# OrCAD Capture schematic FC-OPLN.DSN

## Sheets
1 Index: title: Index
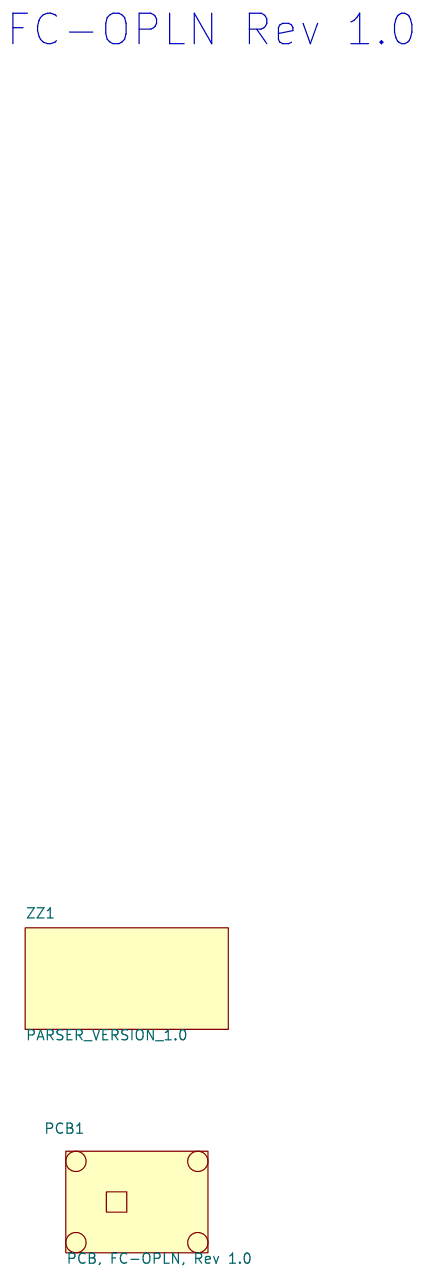
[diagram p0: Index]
2 Block Diagram: title: Block Diagram
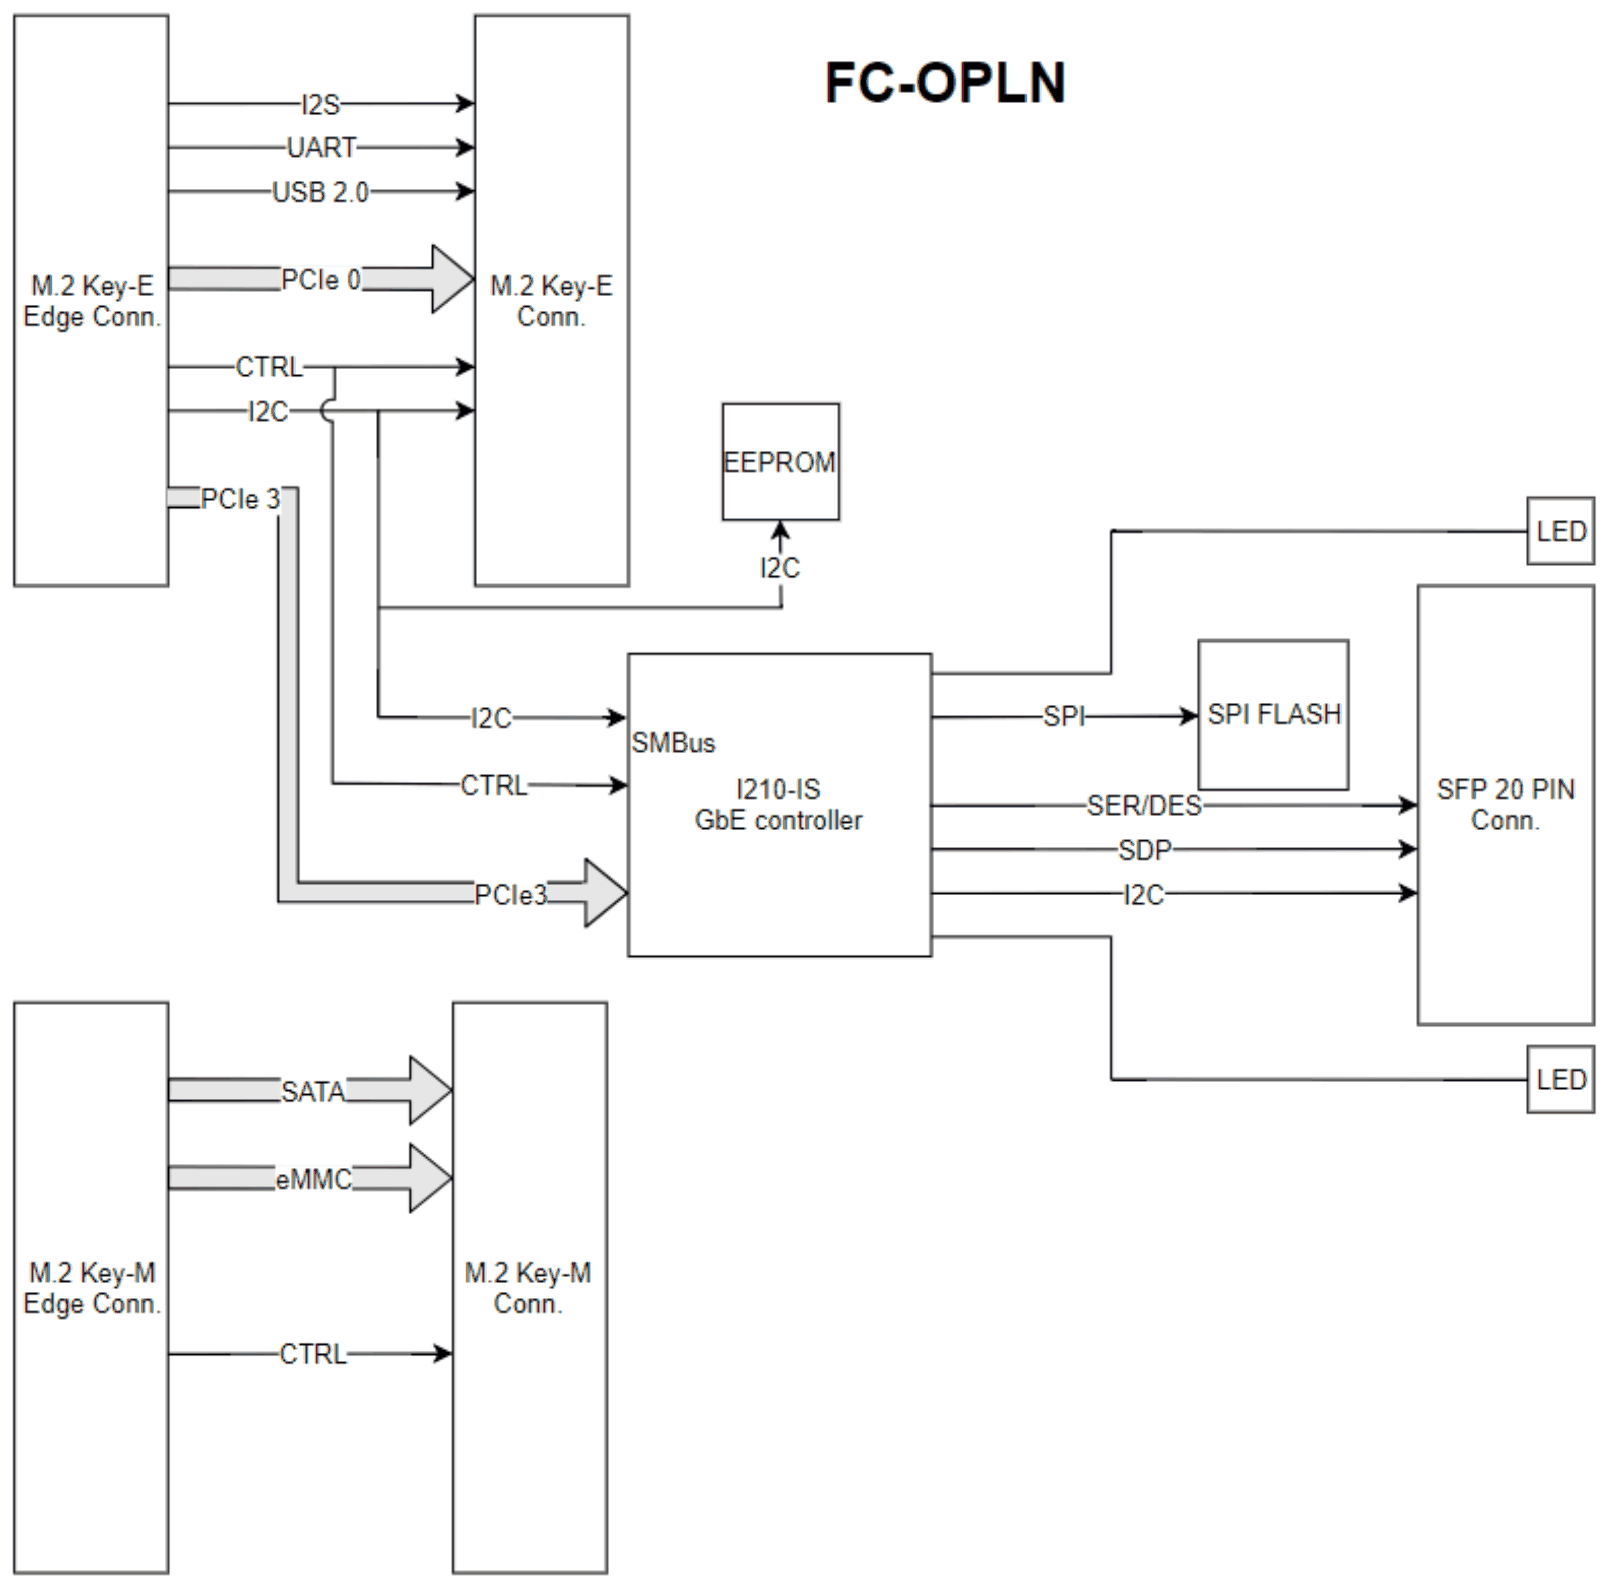
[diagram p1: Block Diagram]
3 Power Diagram
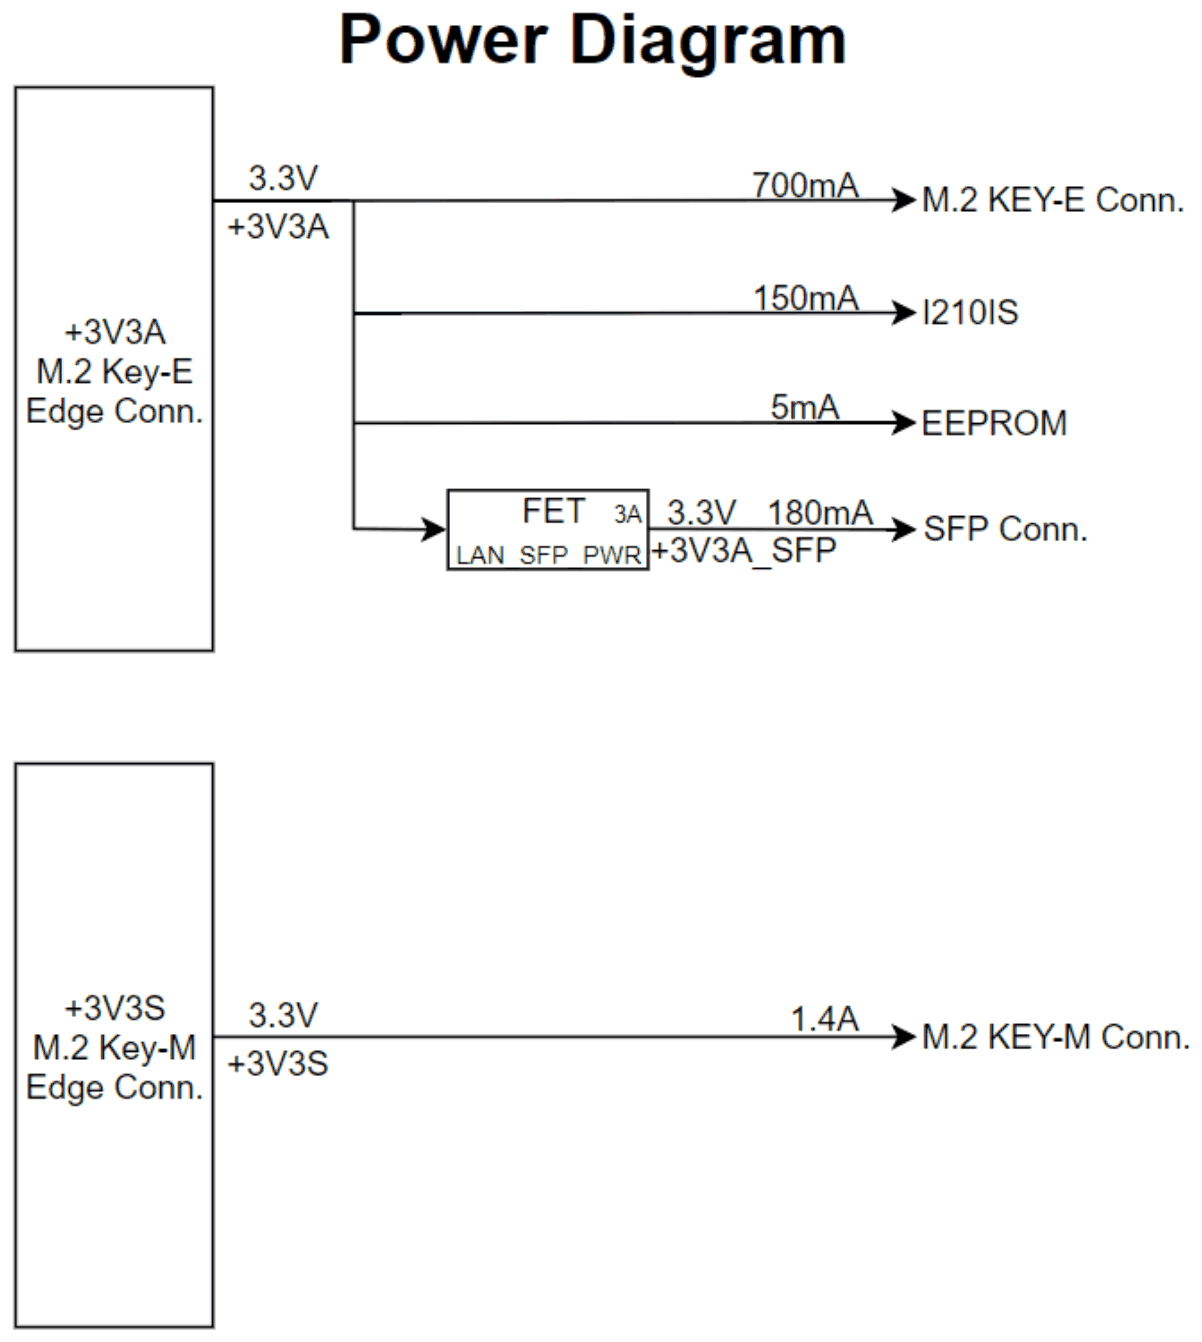
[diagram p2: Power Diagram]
4 M.2 KEY M: size A4; title: M.2 KEY M
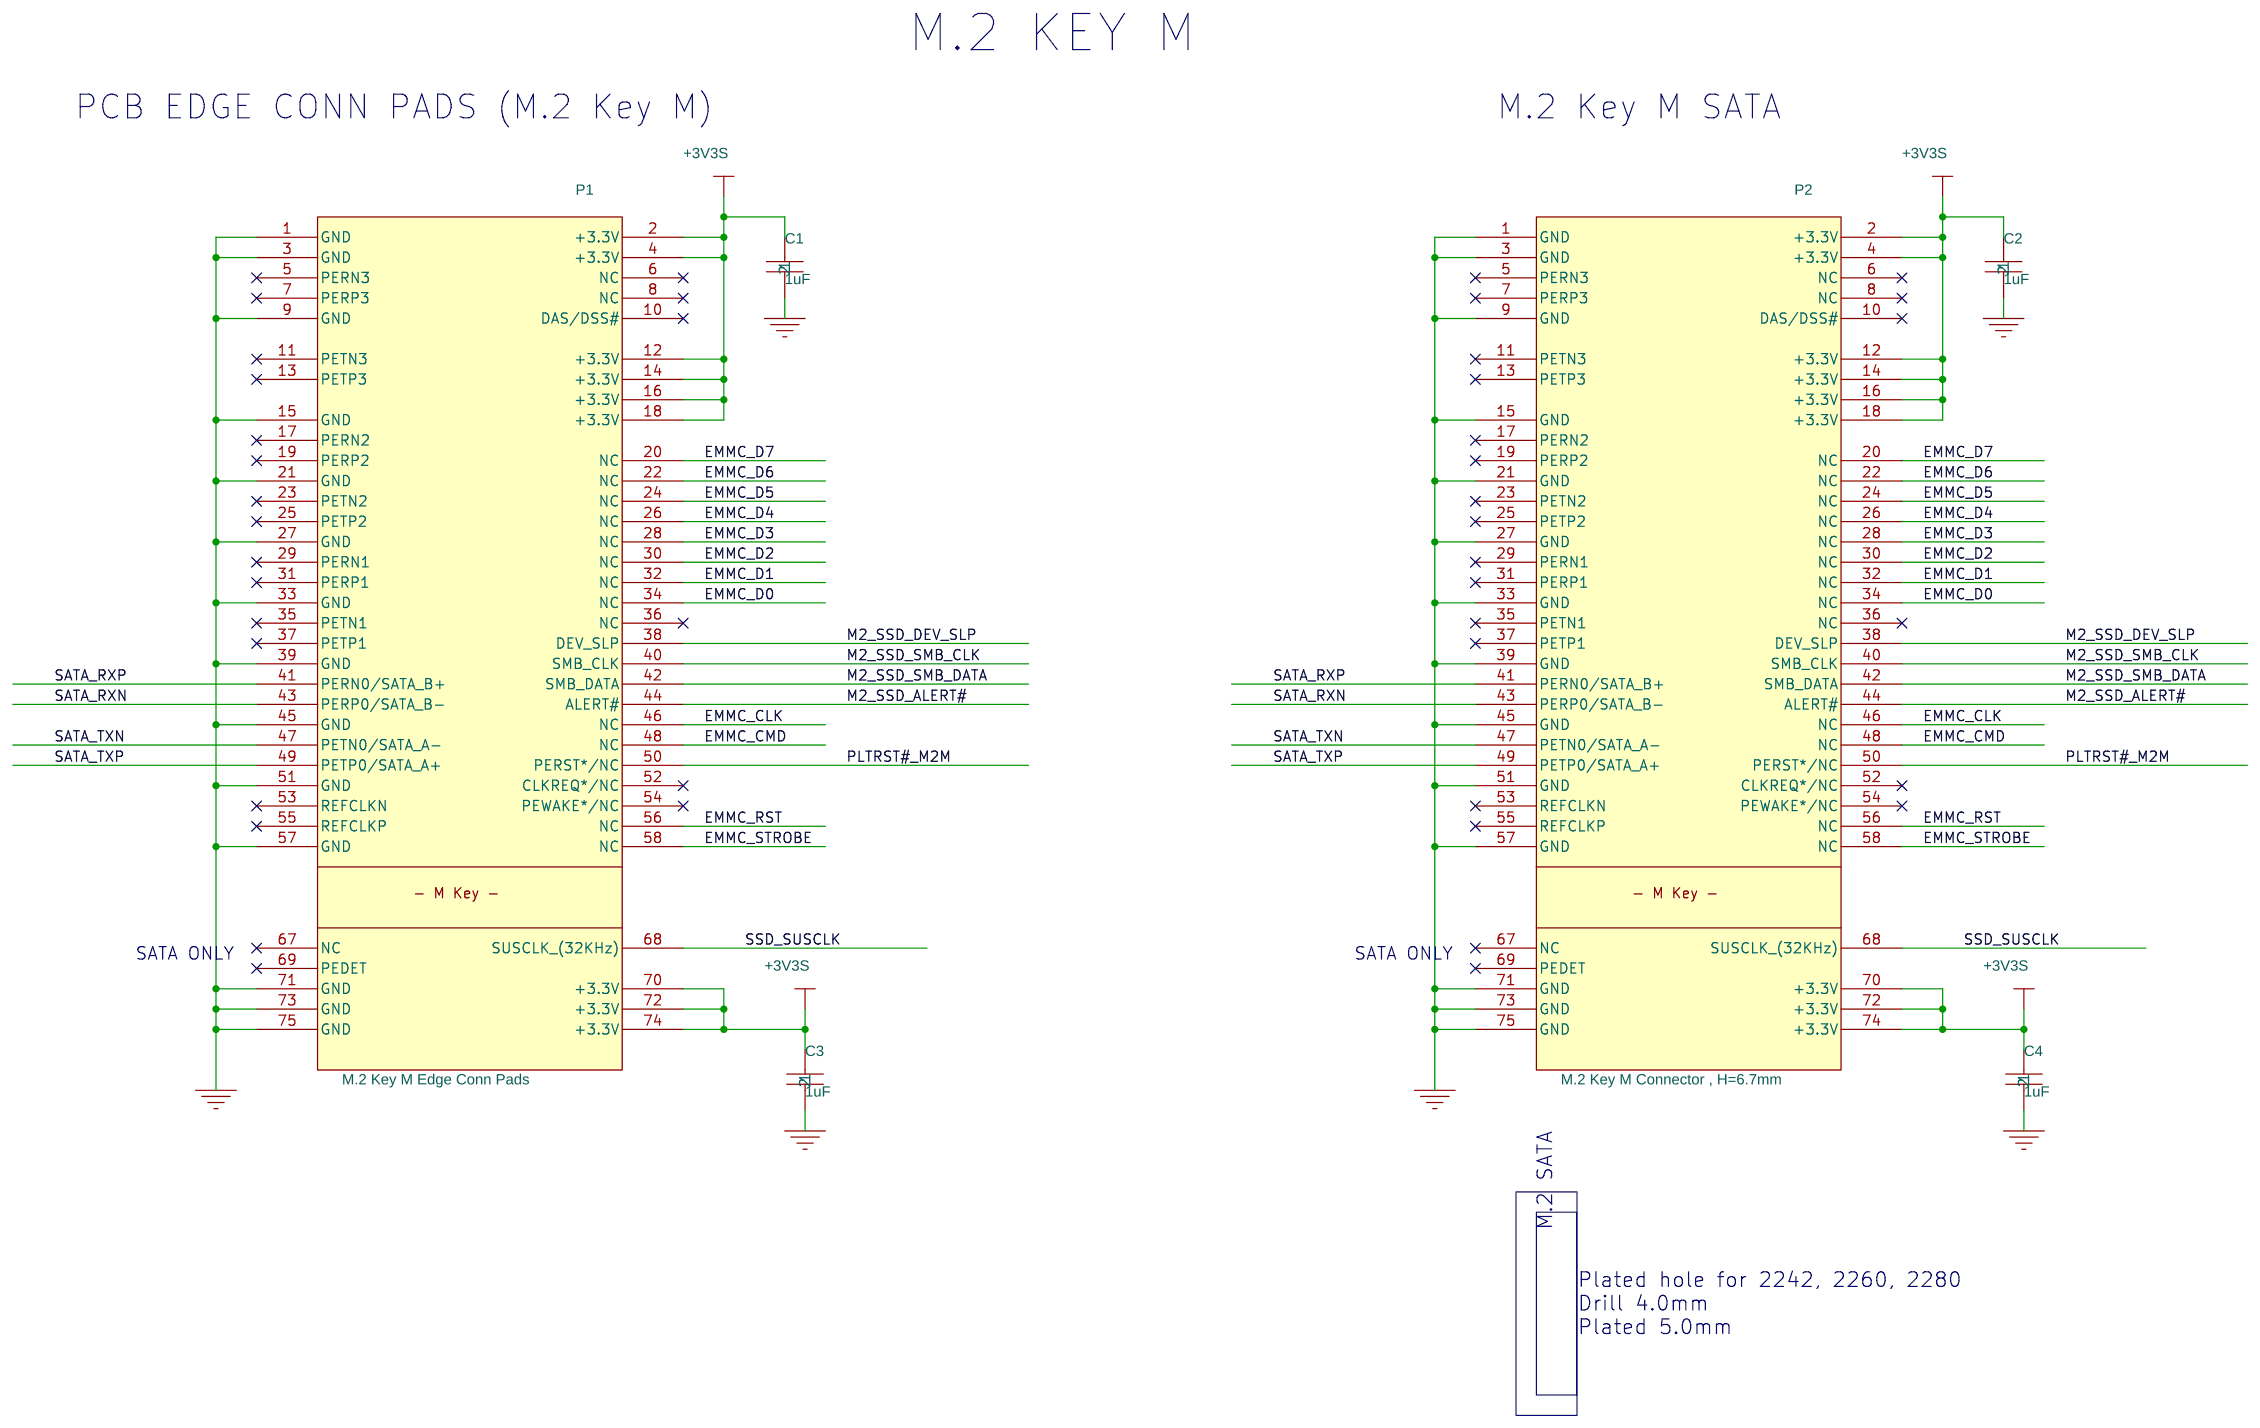
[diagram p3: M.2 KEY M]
5 M.2 KEY E: size A3; title: M.2 KEY E
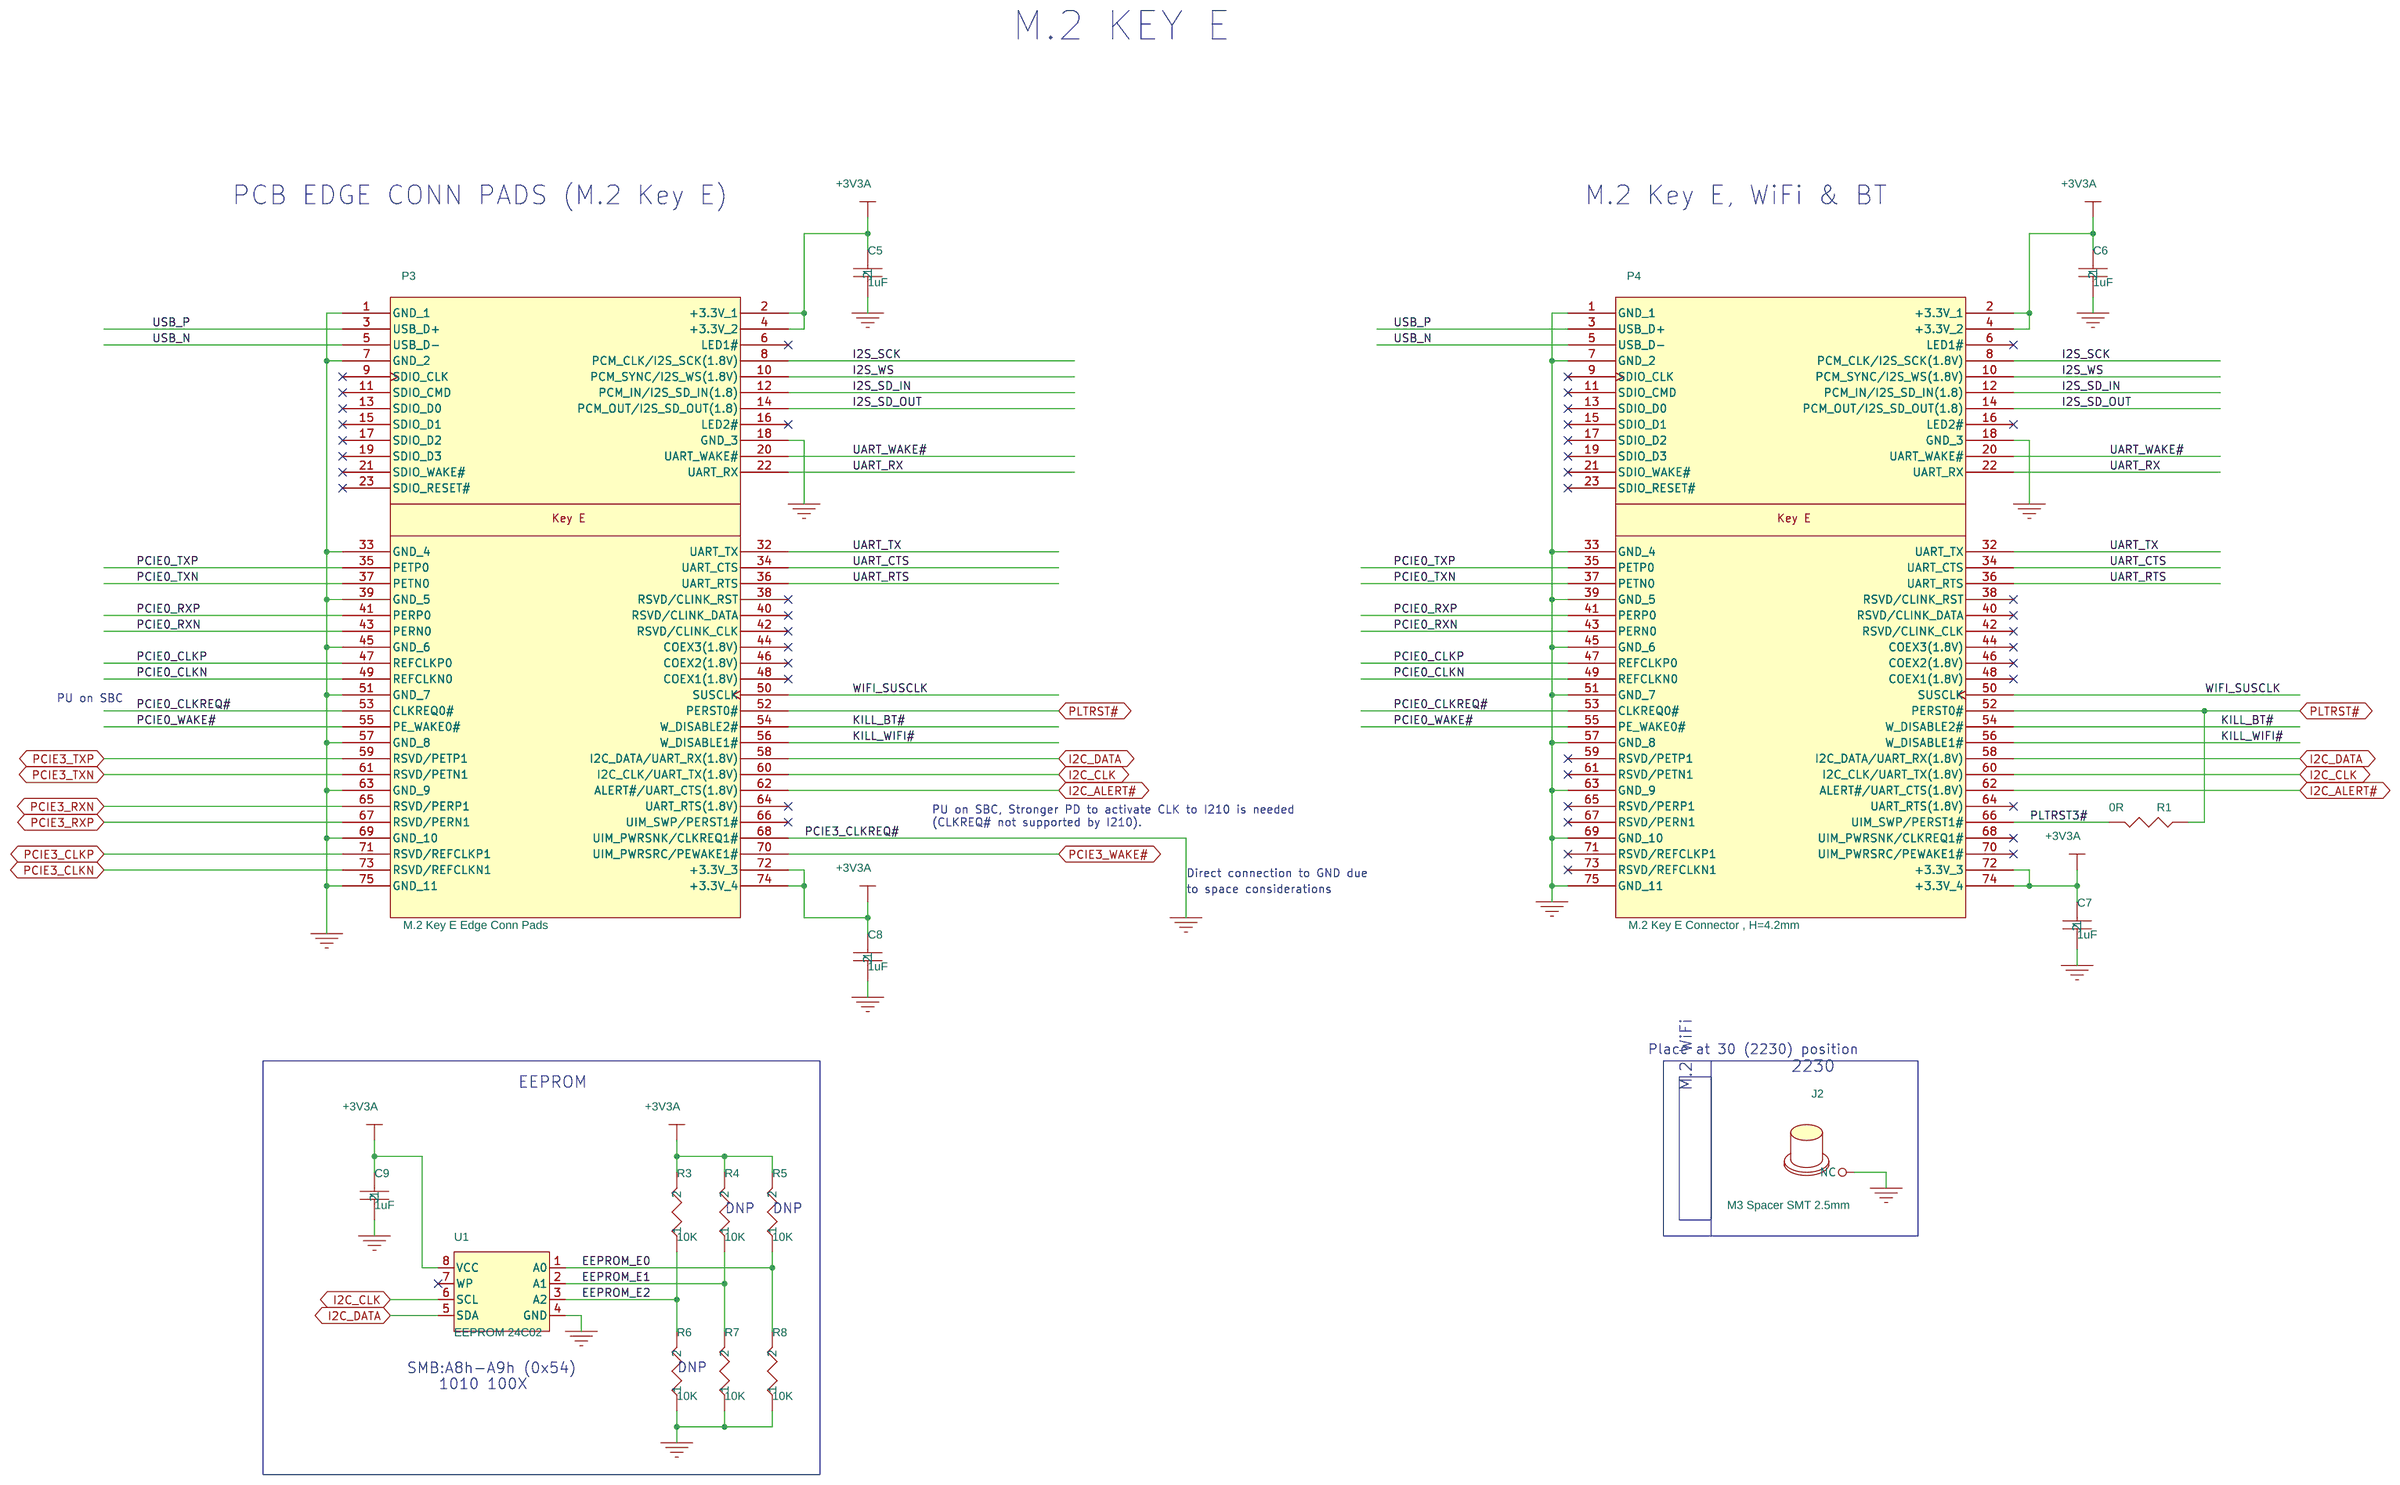
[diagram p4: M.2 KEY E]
6 LAN I210IS: size A3; title: LAN I210IS
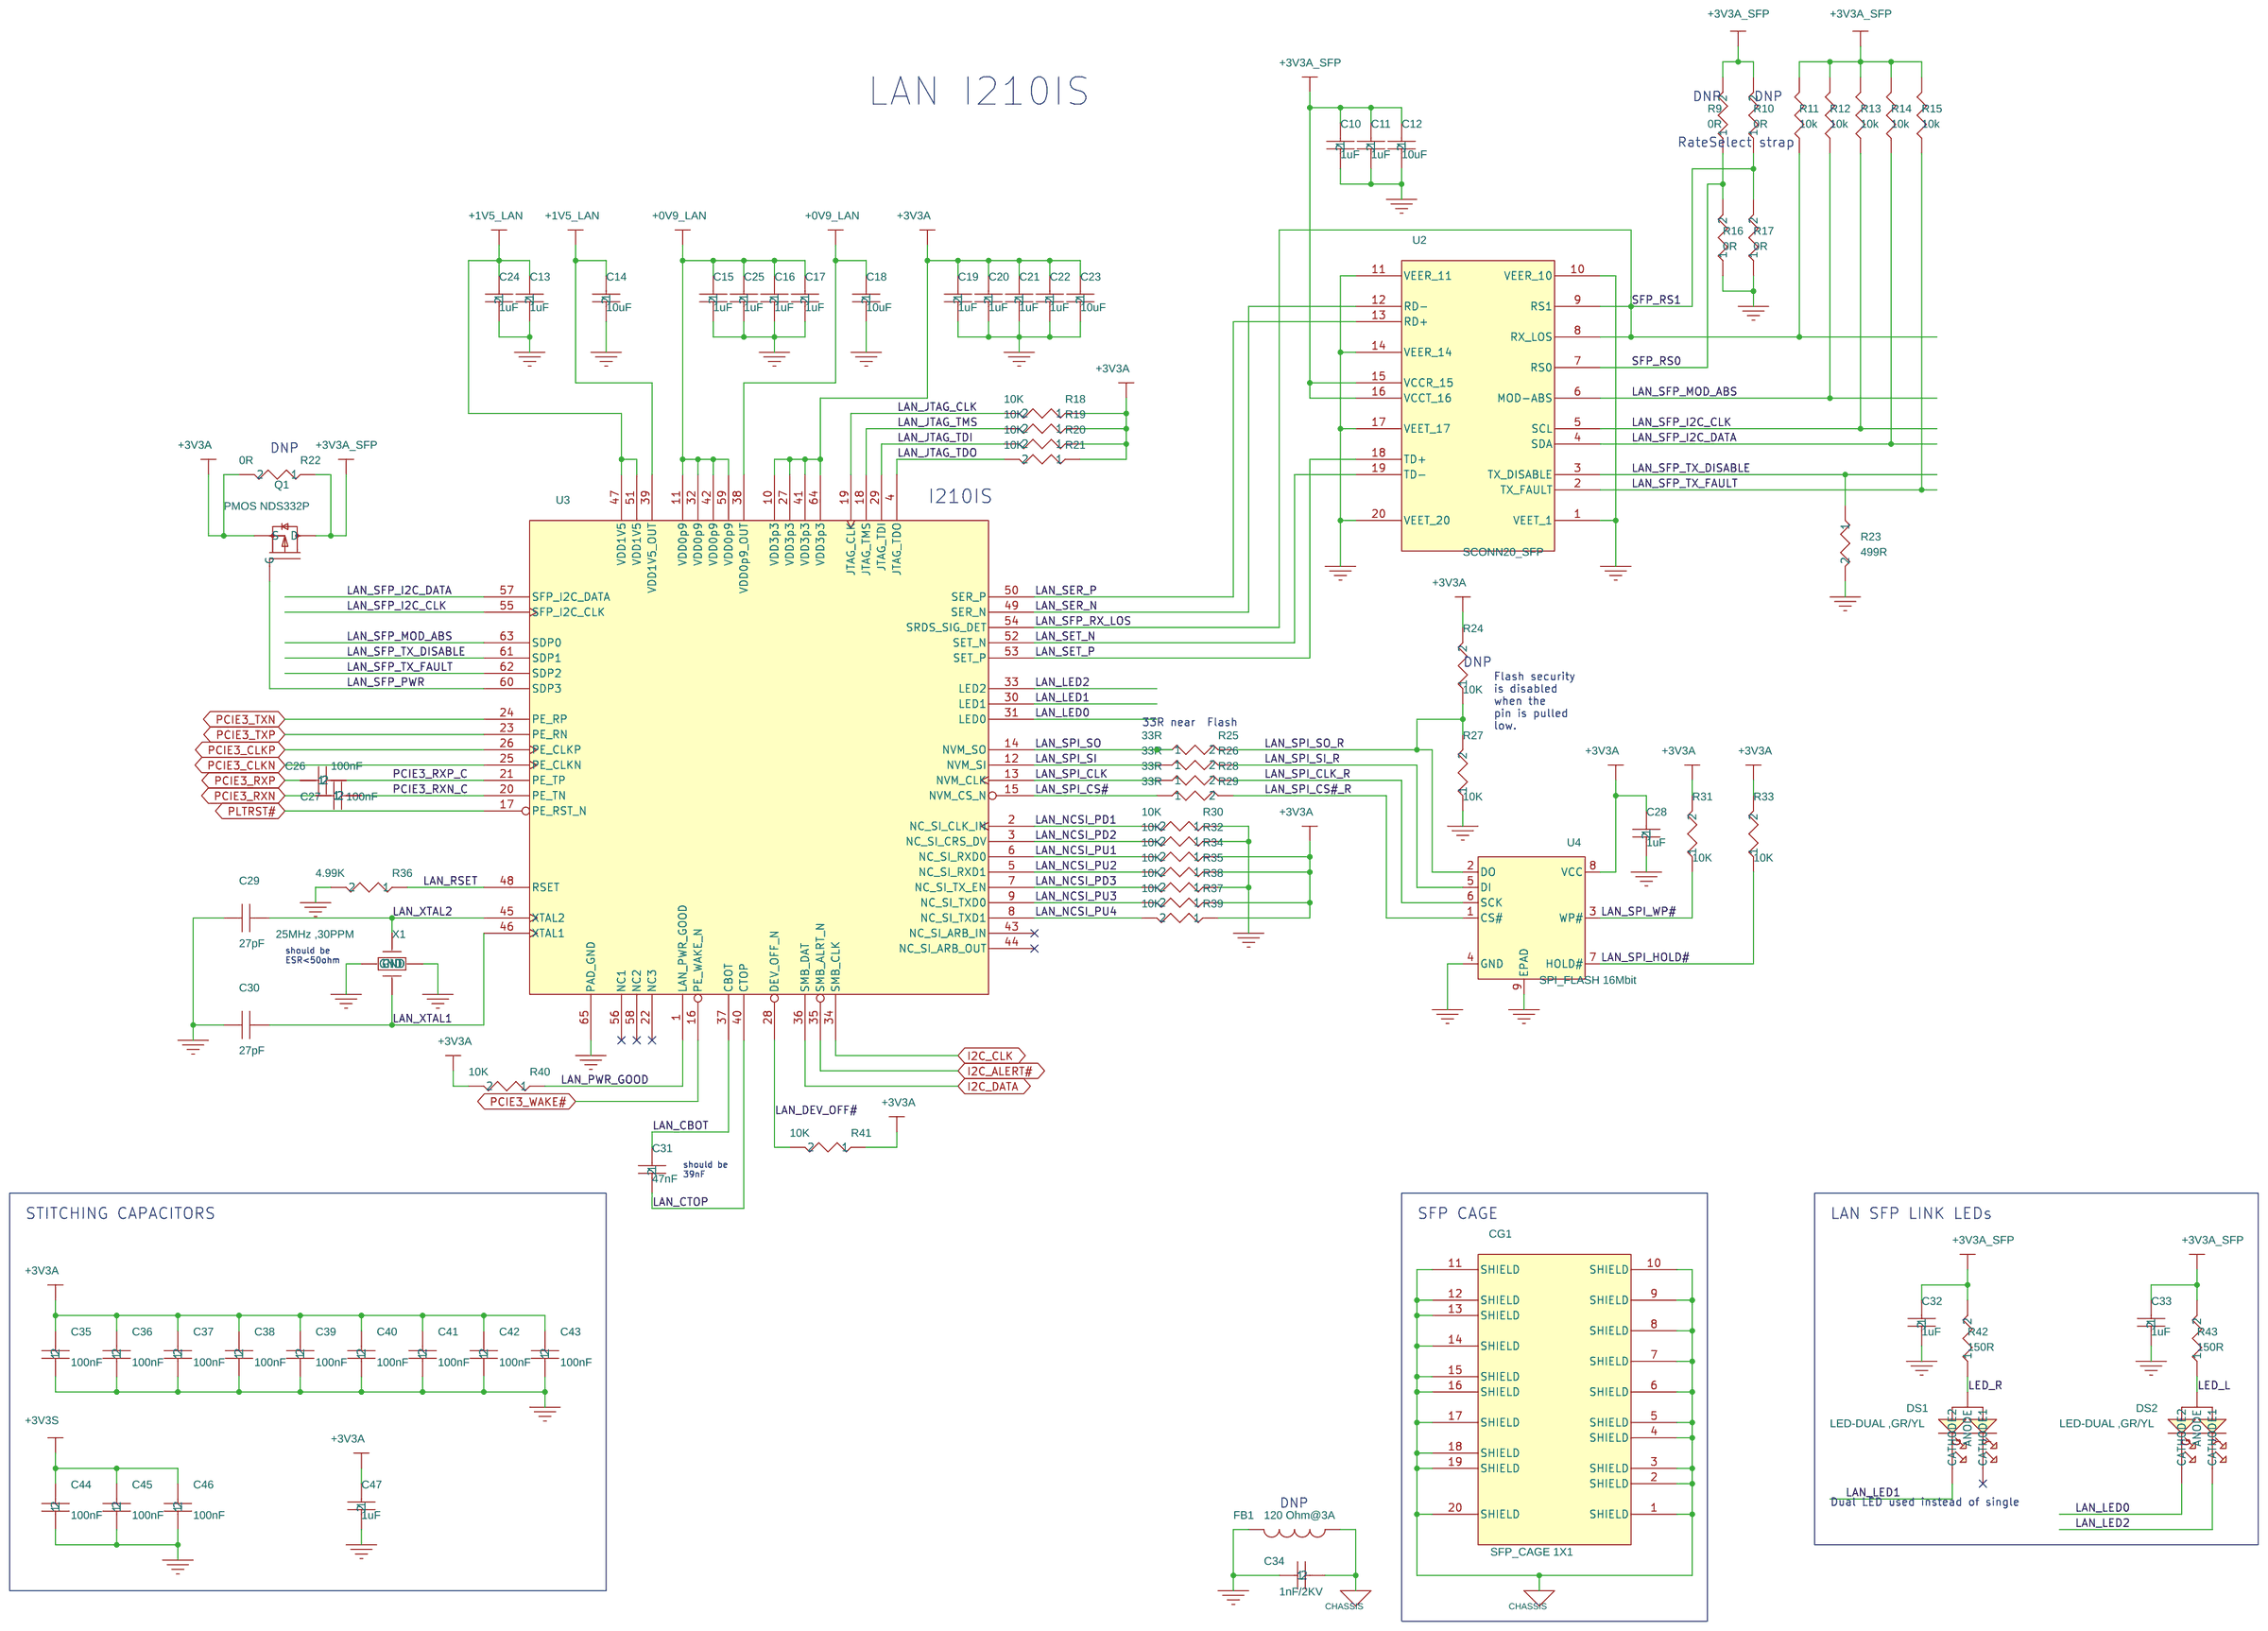
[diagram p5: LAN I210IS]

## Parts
sheet Index
PCB1  PCB, FC-OPLN, Rev 1.0
ZZ1  PARSER_VERSION_1.0
sheet LAN I210IS
C10  1uF  [RC0603]
C11  1uF  [RC0603]
C12  10uF  [RC0603]
C13  1uF  [RC0603]
C14  10uF  [RC0603]
C15  1uF  [RC0603]
C16  1uF  [RC0603]
C17  1uF  [RC0603]
C18  10uF  [RC0603]
C19  1uF  [RC0603]
C20  1uF  [RC0603]
C21  1uF  [RC0603]
C22  1uF  [RC0603]
C23  10uF  [RC0603]
C24  1uF  [RC0603]
C25  1uF  [RC0603]
C26  100nF  [RC0402]
C27  100nF  [RC0402]
C28  1uF  [RC0603]
C29  27pF  [RC0402]
C30  27pF  [RC0402]
C31  47nF  [RC0603]
C32  1uF  [RC0603]
C33  1uF  [RC0603]
C34  1nF/2KV  [C1812]
C35  100nF  [RC0402]
C36  100nF  [RC0402]
C37  100nF  [RC0402]
C38  100nF  [RC0402]
C39  100nF  [RC0402]
C40  100nF  [RC0402]
C41  100nF  [RC0402]
C42  100nF  [RC0402]
C43  100nF  [RC0402]
C44  100nF  [RC0402]
C45  100nF  [RC0402]
C46  100nF  [RC0402]
C47  1uF  [RC0603]
CG1  SFP_CAGE 1X1
DS1  LED-DUAL ,GR/YL  [LED3x1RASM]
DS2  LED-DUAL ,GR/YL  [LED3x1RASM]
FB1  120 Ohm@3A  [1206]
Q1  PMOS NDS332P  [SOT23]
R9  0R  [RC0402]
R10  0R  [RC0402]
R11  10k  [RC0402]
R12  10k  [RC0402]
R13  10k  [RC0402]
R14  10k  [RC0402]
R15  10k  [RC0402]
R16  0R  [RC0402]
R17  0R  [RC0402]
R18  10K  [RC0402]
R19  10K  [RC0402]
R20  10K  [RC0402]
R21  10K  [RC0402]
R22  0R  [RC0402]
R23  499R  [RC0402]
R24  10K  [RC0402]
R25  33R  [RC0402]
R26  33R  [RC0402]
R27  10K  [RC0402]
R28  33R  [RC0402]
R29  33R  [RC0402]
R30  10K  [RC0402]
R31  10K  [RC0402]
R32  10K  [RC0402]
R33  10K  [RC0402]
R34  10K  [RC0402]
R35  10K  [RC0402]
R36  4.99K  [RC0402]
R37  10K  [RC0402]
R38  10K  [RC0402]
R39  10K  [RC0402]
R40  10K  [RC0402]
R41  10K  [RC0402]
R42  150R  [RC0402]
R43  150R  [RC0402]
U2  SCONN20_SFP  [SFP_CONN]
U3  WGI210IS
U4  SPI_FLASH 16Mbit  [WSON5x6-8]
X1  25MHz ,30PPM  [OSC3225]
sheet M.2 KEY E
C5  1uF  [RC0603]
C6  1uF  [RC0603]
C7  1uF  [RC0603]
C8  1uF  [RC0603]
C9  1uF  [RC0603]
J2  M3 Spacer SMT 2.5mm  [SpacerM3TAPSM]
P3  M.2 Key E Edge Conn Pads  [EdgeM2keyE]
P4  M.2 Key E Connector , H=4.2mm  [NGFF67P4HEkeySM]
R1  0R  [RC0402]
R3  10K  [RC0402]
R4  10K  [RC0402]
R5  10K  [RC0402]
R6  10K  [RC0402]
R7  10K  [RC0402]
R8  10K  [RC0402]
U1  EEPROM 24C02  [MO-229VCED-2]
sheet M.2 KEY M
C1  1uF  [RC0603]
C2  1uF  [RC0603]
C3  1uF  [RC0603]
C4  1uF  [RC0603]
P1  M.2 Key M Edge Conn Pads  [EdgeM2keyM]
P2  M.2 Key M Connector , H=6.7mm  [NGFF67P4HMkeySM]

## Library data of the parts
PCB1 = SBC-iHSW_Rev_1.0: CLABCONF0: FC-OPLN; P/N: 188C03260
ZZ1 = PARSER_VERSION_1.0
C4 C8 C10 = 47nF,_25V,_X7R,_10%,_0603_2: CLABCONF0: FC-OPLN; P/N: 151C10500S
C11 = 47nF,_25V,_X7R,_10%,_0603_18: CLABCONF0: FC-OPLN; P/N: 151C10500S
C12 = 47nF,_25V,_X7R,_10%,_0603_13: CLABCONF0: FC-OPLN; P/N: 151B10600S
C13 = 47nF,_25V,_X7R,_10%,_0603_12: CLABCONF0: FC-OPLN; P/N: 151C10500S
C14 = 47nF,_25V,_X7R,_10%,_0603_19: CLABCONF0: FC-OPLN; P/N: 151B10600S
C15 = 47nF,_25V,_X7R,_10%,_0603_5: CLABCONF0: FC-OPLN; P/N: 151C10500S
C16 = 47nF,_25V,_X7R,_10%,_0603_6: CLABCONF0: FC-OPLN; P/N: 151C10500S
C17 = 47nF,_25V,_X7R,_10%,_0603_14: CLABCONF0: FC-OPLN; P/N: 151C10500S
C18 = 47nF,_25V,_X7R,_10%,_0603_8: CLABCONF0: FC-OPLN; P/N: 151B10600S
C19 = 47nF,_25V,_X7R,_10%,_0603_10: CLABCONF0: FC-OPLN; P/N: 151C10500S
C7 C20 = 47nF,_25V,_X7R,_10%,_0603_4: CLABCONF0: FC-OPLN; P/N: 151C10500S
C21 = 47nF,_25V,_X7R,_10%,_0603_20: CLABCONF0: FC-OPLN; P/N: 151C10500S
C22 = 47nF,_25V,_X7R,_10%,_0603_17: CLABCONF0: FC-OPLN; P/N: 151C10500S
C23 = 47nF,_25V,_X7R,_10%,_0603_7: CLABCONF0: FC-OPLN; P/N: 151B10600S
C3 C9 C24 = 47nF,_25V,_X7R,_10%,_0603_1: CLABCONF0: FC-OPLN; P/N: 151C10500S
C2 C5 C25 = 47nF,_25V,_X7R,_10%,_0603: CLABCONF0: FC-OPLN; P/N: 151C10500S
C26 = 100nF,_10V,_X7R,_10%,_0402_5: CLABCONF0: FC-OPLN
C27 = 100nF,_10V,_X7R,_10%,_0402_12: CLABCONF0: FC-OPLN
C28 = 47nF,_25V,_X7R,_10%,_0603_11: CLABCONF0: FC-OPLN; P/N: 151C10500S
C29 C30 = 27pF,_50V,_X7R,_10%,_0402: CLABCONF0: FC-OPLN; P/N: 151D27000S
C31 = 47nF,_25V,_X7R,_10%,_0603_9: CLABCONF0: FC-OPLN; P/N: 151C47300S
C1 C6 C32 = 47nF,_25V,_X7R,_10%,_0603_3: CLABCONF0: FC-OPLN; P/N: 151C10500S
C33 = 47nF,_25V,_X7R,_10%,_0603_15: CLABCONF0: FC-OPLN; P/N: 151C10500S
C34 = 1nF,_2KV,SMD_1812,_X7R,_10%_0: CLABCONF0: FC-OPLN
C35 = 100nF,_10V,_X7R,_10%,_0402_11: CLABCONF0: FC-OPLN
C36 = 100nF,_10V,_X7R,_10%,_0402_7: CLABCONF0: FC-OPLN
C37 = 100nF,_10V,_X7R,_10%,_0402_8: CLABCONF0: FC-OPLN
C38 = 100nF,_10V,_X7R,_10%,_0402_1: CLABCONF0: FC-OPLN
C39 = 100nF,_10V,_X7R,_10%,_0402_13: CLABCONF0: FC-OPLN
C40 = 100nF,_10V,_X7R,_10%,_0402_2: CLABCONF0: FC-OPLN
C41 = 100nF,_10V,_X7R,_10%,_0402_6: CLABCONF0: FC-OPLN
C42 = 100nF,_10V,_X7R,_10%,_0402_4: CLABCONF0: FC-OPLN
C43 = 100nF,_10V,_X7R,_10%,_0402: CLABCONF0: FC-OPLN
C44 = 100nF,_10V,_X7R,_10%,_0402_9: CLABCONF0: FC-OPLN
C45 = 100nF,_10V,_X7R,_10%,_0402_3: CLABCONF0: FC-OPLN
C46 = 100nF,_10V,_X7R,_10%,_0402_10: CLABCONF0: FC-OPLN
C47 = 47nF,_25V,_X7R,_10%,_0603_16: CLABCONF0: FC-OPLN; P/N: 151C10500S
CG1 = SFP_CAGE_0: CLABCONF0: FC-OPLN; P/N: 203H10050
DS1 DS2 = LED,_Dual,ip_3x1mm,_R_A,_G_Y: CLABCONF0: FC-OPLN
FB1 = Ferrite_bead_,_120_Ohm@3A_0: CLABCONF0: DNP
Q1 = P-MOSFET,3A,20V,110mOhm@-1.8V: CLABCONF0: FC-OPLN
R9 = 0R,_0402_0_1: CLABCONF0: DNP
R10 = 0R,_0402_0_4: CLABCONF0: DNP
R11-R15 = 1M_,5%,_0402_0: CLABCONF0: FC-OPLN; P/N: 161C10021S
R16 = 0R,_0402_0_3: CLABCONF0: FC-OPLN
R17 = 0R,_0402_0: CLABCONF0: FC-OPLN
R18 = 0R_14: CLABCONF0: FC-OPLN; P/N: 161C10021S
R19 = 0R_10: CLABCONF0: FC-OPLN; P/N: 161C10021S
R20 = 0R_9: CLABCONF0: FC-OPLN; P/N: 161C10021S
R21 = 0R_8: CLABCONF0: FC-OPLN; P/N: 161C10021S
R22 = 0R,_0402_0_2: CLABCONF0: FC-OPLN
R23 = 75R,1%,0402,1_16W: CLABCONF0: FC-OPLN; Group: POWER_48; P/N: 161C49901S
R24 = 0R_19: CLABCONF0: DNP; P/N: 161C10021S
R25 = 0R_18: CLABCONF0: FC-OPLN; P/N: 161C33R05S
R26 = 0R_5: CLABCONF0: FC-OPLN; P/N: 161C33R05S
R27 = 0R_22: CLABCONF0: FC-OPLN; P/N: 161C10021S
R28 = 0R_17: CLABCONF0: FC-OPLN; P/N: 161C33R05S
R29 = 0R_21: CLABCONF0: FC-OPLN; P/N: 161C33R05S
R30 = 0R_11: CLABCONF0: FC-OPLN; P/N: 161C10021S
R31 = 0R_16: CLABCONF0: FC-OPLN; P/N: 161C10021S
R8 R32 = 0R_1: CLABCONF0: FC-OPLN; P/N: 161C10021S
R3 R33 = 0R_2: CLABCONF0: FC-OPLN; P/N: 161C10021S
R7 R34 = 0R_4: CLABCONF0: FC-OPLN; P/N: 161C10021S
R35 = 0R_7: CLABCONF0: FC-OPLN; P/N: 161C10021S
R36 = 0R_15: CLABCONF0: FC-OPLN; P/N: 161C49911S
R37 = 0R_23: CLABCONF0: FC-OPLN; P/N: 161C10021S
R38 = 0R_13: CLABCONF0: FC-OPLN; P/N: 161C10021S
R39 = 0R_3: CLABCONF0: FC-OPLN; P/N: 161C10021S
R40 = 0R_6: CLABCONF0: FC-OPLN; P/N: 161C10021S
R41 = 0R_12: CLABCONF0: FC-OPLN; P/N: 161C10021S
R42 = 0R: CLABCONF0: FC-OPLN; P/N: 161C15001S
R43 = 0R_20: CLABCONF0: FC-OPLN; P/N: 161C15001S
U2 = SCONN20_SFP: CLABCONF0: FC-OPLN; P/N: 184K02000S
U3 = I210IS_0: CLABCONF0: FC-OPLN; P/N: 116B00072S
U4 = IC,FLASH,SPI,64MBit_0: CLABCONF0: FC-OPLN; P/N: 111S32100I
X1 = TMP_133032: CLABCONF0: FC-OPLN; P/N: 141B25603I
J2 = Spacer_SMT,_M2,_4mm: CLABCONF0: FC-OPLN; P/N: 383B54510S
P3 = Conn.,_M.2_Key_E_PCIe: CLABCONF0: FC-OPLN; P/N: NA2
P4 = Conn.,_M.2_Key_E_PCIe: CLABCONF0: FC-OPLN; P/N: 182K06701S
R1 = 0R_0: CLABCONF0: FC-OPLN
R4 = 0R_5: CLABCONF0: DNP; P/N: 161C10021S
R5 = 0R_3: CLABCONF0: DNP; P/N: 161C10021S
R6 = 0R: CLABCONF0: DNP; P/N: 161C10021S
U1 = 24C02,_serial_EE,_2KB,_I2C: CLABCONF0: FC-OPLN; P/N: 111S30801S
P1 = Conn.,_M_0.2_Key_M_SATA_PCIex4: CLABCONF0: FC-OPLN; P/N: NA1
P2 = Conn.,_M_0.2_Key_M_SATA_PCIex4: CLABCONF0: FC-OPLN; P/N: 182K06706S

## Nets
+0V9_LAN: C15.1 C16.1 C17.1 C18.1 C25.1 U3.11(VDD0p9) U3.32(VDD0p9) U3.38(VDD0p9_OUT) U3.42(VDD0p9) U3.59(VDD0p9)
+1V5_LAN: C13.1 C14.1 C24.1 U3.39(VDD1V5_OUT) U3.47(VDD1V5) U3.51(VDD1V5)
+3V3A: C5.1 C6.1 C7.1 C8.1 C9.1 C19.1 C20.1 C21.1 C22.1 C23.1 C28.1 C35.2 C36.2 C37.2 C38.2 C39.2 C40.2 C41.2 C42.2 C43.2 C47.1 P3.2(+3.3V_1) P3.4(+3.3V_2) P3.72(+3.3V_3) P3.74(+3.3V_4) P4.2(+3.3V_1) P4.4(+3.3V_2) P4.72(+3.3V_3) P4.74(+3.3V_4) Q1.2(S) R3.2 R4.2 R5.2 R18.1 R19.1 R20.1 R21.1 R22.2 R24.2 R31.2 R33.2 R34.1 R35.1 R37.1 R39.1 R40.2 R41.1 U1.8(VCC) U3.10(VDD3p3) U3.27(VDD3p3) U3.41(VDD3p3) U3.64(VDD3p3) U4.8(VCC)
+3V3A_SFP: C10.1 C11.1 C12.1 C32.1 C33.1 Q1.3(D) R9.2 R10.2 R11.2 R12.2 R13.2 R14.2 R15.2 R22.1 R42.2 R43.2 U2.15(VCCR) U2.16(VCCT)
+3V3S: C1.1 C2.1 C3.1 C4.1 C44.2 C45.2 C46.2 P1.2(+3.3V) P1.4(+3.3V) P1.12(+3.3V) P1.14(+3.3V) P1.16(+3.3V) P1.18(+3.3V) P1.70(+3.3V) P1.72(+3.3V) P1.74(+3.3V) P2.2(+3.3V) P2.4(+3.3V) P2.12(+3.3V) P2.14(+3.3V) P2.16(+3.3V) P2.18(+3.3V) P2.70(+3.3V) P2.72(+3.3V) P2.74(+3.3V)
GND: C1.2 C2.2 C3.2 C4.2 C5.2 C6.2 C7.2 C8.2 C9.2 C10.2 C11.2 C12.2 C13.2 C14.2 C15.2 C16.2 C17.2 C18.2 C19.2 C20.2 C21.2 C22.2 C23.2 C24.2 C25.2 C28.2 C29.1 C30.1 C32.2 C33.2 C34.1 C35.1 C36.1 C37.1 C38.1 C39.1 C40.1 C41.1 C42.1 C43.1 C44.1 C45.1 C46.1 C47.2 FB1.2 J2.NC P1.1(GND) P1.3(GND) P1.9(GND) P1.15(GND) P1.21(GND) P1.27(GND) P1.33(GND) P1.39(GND) P1.45(GND) P1.51(GND) P1.57(GND) P1.71(GND) P1.73(GND) P1.75(GND) P2.1(GND) P2.3(GND) P2.9(GND) P2.15(GND) P2.21(GND) P2.27(GND) P2.33(GND) P2.39(GND) P2.45(GND) P2.51(GND) P2.57(GND) P2.71(GND) P2.73(GND) P2.75(GND) P3.1(GND) P3.7(GND_2) P3.18(GND_3) P3.33(GND_4) P3.39(GND_5) P3.45(GND_6) P3.51(GND_7) P3.57(GND_8) P3.63(GND_9) P3.68(UIM_PWRSNK/CLKREQ1#) P3.69(GND_10) P3.75(GND_11) P4.1(GND) P4.7(GND_2) P4.18(GND_3) P4.33(GND_4) P4.39(GND_5) P4.45(GND_6) P4.51(GND_7) P4.57(GND_8) P4.63(GND_9) P4.69(GND_10) P4.75(GND_11) R6.1 R7.1 R8.1 R16.1 R17.1 R23.2 R27.1 R30.1 R32.1 R36.2 R38.1 U1.4(GND) U2.1(VEET) U2.10(VEER) U2.11(VEER) U2.14(VEER) U2.17(VEET) U2.20(VEET) U3.65(PAD_GND) U4.4(GND) U4.9(EPAD) X1.2(GND) X1.4(GND)
CHASSIS: C34.2 CG1.1(SHIELD) CG1.2(SHIELD) CG1.3(SHIELD) CG1.4(SHIELD) CG1.5(SHIELD) CG1.6(SHIELD) CG1.7(SHIELD) CG1.8(SHIELD) CG1.9(SHIELD) CG1.10(SHIELD) CG1.11(SHIELD) CG1.12(SHIELD) CG1.13(SHIELD) CG1.14(SHIELD) CG1.15(SHIELD) CG1.16(SHIELD) CG1.17(SHIELD) CG1.18(SHIELD) CG1.19(SHIELD) CG1.20(SHIELD) FB1.1
EEPROM_E0: R5.1 R8.2 U1.1(A0)
EEPROM_E1: R4.1 R7.2 U1.2(A1)
EEPROM_E2: R3.1 R6.2 U1.3(A2)
EMMC_CLK: P1.46(NC) P2.46(NC)
EMMC_CMD: P1.48(NC) P2.48(NC)
EMMC_D0: P1.34(NC) P2.34(NC)
EMMC_D1: P1.32(NC) P2.32(NC)
EMMC_D2: P1.30(NC) P2.30(NC)
EMMC_D3: P1.28(NC) P2.28(NC)
EMMC_D4: P1.26(NC) P2.26(NC)
EMMC_D5: P1.24(NC) P2.24(NC)
EMMC_D6: P1.22(NC) P2.22(NC)
EMMC_D7: P1.20(NC) P2.20(NC)
EMMC_RST: P1.56(NC) P2.56(NC)
EMMC_STROBE: P1.58(NC) P2.58(NC)
I2C_ALERT#: P3.62(ALERT#/UART_CTS(1.8V)) P4.62(ALERT#/UART_CTS(1.8V)) U3.35(SMB_ALRT_N)
I2C_CLK: P3.60(I2C_CLK/UART_TX(1.8V)) P4.60(I2C_CLK/UART_TX(1.8V)) U1.6(SCL) U3.34(SMB_CLK)
I2C_DATA: P3.58(I2C_DATA/UART_RX(1.8V)) P4.58(I2C_DATA/UART_RX(1.8V)) U1.5(SDA) U3.36(SMB_DAT)
I2S_SCK: P3.8(PCM_CLK/I2S_SCK(1.8V)) P4.8(PCM_CLK/I2S_SCK(1.8V))
I2S_SD_IN: P3.12(PCM_IN/I2S_SD_IN(1.8)) P4.12(PCM_IN/I2S_SD_IN(1.8))
I2S_SD_OUT: P3.14(PCM_OUT/I2S_SD_OUT(1.8)) P4.14(PCM_OUT/I2S_SD_OUT(1.8))
I2S_WS: P3.10(PCM_SYNC/I2S_WS(1.8V)) P4.10(PCM_SYNC/I2S_WS(1.8V))
KILL_BT#: P3.54(W_DISABLE2#) P4.54(W_DISABLE2#)
KILL_WIFI#: P3.56(W_DISABLE1#) P4.56(W_DISABLE1#)
LAN_CBOT: C31.1 U3.37(CBOT)
LAN_CTOP: C31.2 U3.40(CTOP)
LAN_DEV_OFF#: R41.2 U3.28(DEV_OFF_N)
LAN_JTAG_CLK: R18.2 U3.19(JTAG_CLK)
LAN_JTAG_TDI: R20.2 U3.29(JTAG_TDI)
LAN_JTAG_TDO: R21.2 U3.4(JTAG_TDO)
LAN_JTAG_TMS: R19.2 U3.18(JTAG_TMS)
LAN_LED0: DS2.C2(CATHODE2) U3.31(LED0)
LAN_LED1: DS1.C2(CATHODE2) U3.30(LED1)
LAN_LED2: DS2.C1(CATHODE1) U3.33(LED2)
LAN_NCSI_PD1: R30.2 U3.2(NC_SI_CLK_IN)
LAN_NCSI_PD2: R32.2 U3.3(NC_SI_CRS_DV)
LAN_NCSI_PD3: R38.2 U3.7(NC_SI_TX_EN)
LAN_NCSI_PU1: R34.2 U3.6(NC_SI_RXD0)
LAN_NCSI_PU2: R35.2 U3.5(NC_SI_RXD1)
LAN_NCSI_PU3: R37.2 U3.9(NC_SI_TXD0)
LAN_NCSI_PU4: R39.2 U3.8(NC_SI_TXD1)
LAN_PWR_GOOD: R40.1 U3.1(LAN_PWR_GOOD)
LAN_RSET: R36.1 U3.48(RSET)
LAN_SER_N: U2.12(RD-) U3.49(SER_N)
LAN_SER_P: U2.13(RD+) U3.50(SER_P)
LAN_SET_N: U2.19(TD-) U3.52(SET_N)
LAN_SET_P: U2.18(TD+) U3.53(SET_P)
LAN_SFP_I2C_CLK: R13.1 U2.5(SCL) U3.55(SFP_I2C_CLK)
LAN_SFP_I2C_DATA: R14.1 U2.4(SDA) U3.57(SFP_I2C_DATA)
LAN_SFP_MOD_ABS: R12.1 U2.6(MOD-ABS) U3.63(SDP0)
LAN_SFP_PWR: Q1.1(G) U3.60(SDP3)
LAN_SFP_RX_LOS: R11.1 U2.8(RX_LOS) U3.54(SRDS_SIG_DET)
LAN_SFP_TX_DISABLE: R23.1 U2.3(TX_DISABLE) U3.61(SDP1)
LAN_SFP_TX_FAULT: R15.1 U2.2(TX_FAULT) U3.62(SDP2)
LAN_SPI_CLK: R28.1 U3.13(NVM_CLK)
LAN_SPI_CLK_R: R28.2 U4.6(SCK)
LAN_SPI_CS#: R29.1 U3.15(NVM_CS_N)
LAN_SPI_CS#_R: R29.2 U4.1(CS#)
LAN_SPI_HOLD#: R33.1 U4.7(HOLD#)
LAN_SPI_SI: R26.1 U3.12(NVM_SI)
LAN_SPI_SI_R: R26.2 U4.5(DI)
LAN_SPI_SO: R25.1 U3.14(NVM_SO)
LAN_SPI_SO_R: R24.1 R25.2 R27.2 U4.2(DO)
LAN_SPI_WP#: R31.1 U4.3(WP#)
LAN_XTAL1: C30.2 U3.46(XTAL1) X1.3
LAN_XTAL2: C29.2 U3.45(XTAL2) X1.1
LED_L: DS2.A(ANODE) R43.1
LED_R: DS1.A(ANODE) R42.1
M2_SSD_ALERT#: P1.44(ALERT#) P2.44(ALERT#)
M2_SSD_DEV_SLP: P1.38(DEV_SLP) P2.38(DEV_SLP)
M2_SSD_SMB_CLK: P1.40(SMB_CLK) P2.40(SMB_CLK)
M2_SSD_SMB_DATA: P1.42(SMB_DATA) P2.42(SMB_DATA)
PCIE0_CLKN: P3.49(REFCLKN0) P4.49(REFCLKN0)
PCIE0_CLKP: P3.47(REFCLKP0) P4.47(REFCLKP0)
PCIE0_CLKREQ#: P3.53(CLKREQ0#) P4.53(CLKREQ0#)
PCIE0_RXN: P3.43(PERN0) P4.43(PERN0)
PCIE0_RXP: P3.41(PERP0) P4.41(PERP0)
PCIE0_TXN: P3.37(PETN0) P4.37(PETN0)
PCIE0_TXP: P3.35(PETP0) P4.35(PETP0)
PCIE0_WAKE#: P3.55(PE_WAKE0#) P4.55(PE_WAKE0#)
PCIE3_CLKN: P3.73(RSVD/REFCLKN1) U3.25(PE_CLKN)
PCIE3_CLKP: P3.71(RSVD/REFCLKP1) U3.26(PE_CLKP)
PCIE3_RXN: C27.1 P3.65(RSVD/PERP1)
PCIE3_RXN_C: C27.2 U3.20(PE_TN)
PCIE3_RXP: C26.1 P3.67(RSVD/PERN1)
PCIE3_RXP_C: C26.2 U3.21(PE_TP)
PCIE3_TXN: P3.61(RSVD/PETN1) U3.24(PE_RP)
PCIE3_TXP: P3.59(RSVD/PETP1) U3.23(PE_RN)
PCIE3_WAKE#: P3.70(UIM_PWRSRC/PEWAKE1#) U3.16(PE_WAKE_N)
PLTRST3#: P4.66(UIM_SWP/PERST1#) R1.2
PLTRST#: P3.52(PERST0#) P4.52(PERST0#) R1.1 U3.17(PE_RST_N)
PLTRST#_M2M: P1.50(PERST*/NC) P2.50(PERST*/NC)
SATA_RXN: P1.43(PERP0/SATA_B-) P2.43(PERP0/SATA_B-)
SATA_RXP: P1.41(PERN0/SATA_B+) P2.41(PERN0/SATA_B+)
SATA_TXN: P1.47(PETN0/SATA_A-) P2.47(PETN0/SATA_A-)
SATA_TXP: P1.49(PETP0/SATA_A+) P2.49(PETP0/SATA_A+)
SFP_RS0: R9.1 R16.2 U2.7(RS0)
SFP_RS1: R10.1 R17.2 U2.9(RS1)
SSD_SUSCLK: P1.68(SUSCLK_(32KHz)) P2.68(SUSCLK_(32KHz))
UART_CTS: P3.34(UART_CTS) P4.34(UART_CTS)
UART_RTS: P3.36(UART_RTS) P4.36(UART_RTS)
UART_RX: P3.22(UART_RX) P4.22(UART_RX)
UART_TX: P3.32(UART_TX) P4.32(UART_TX)
UART_WAKE#: P3.20(UART_WAKE#) P4.20(UART_WAKE#)
USB_N: P3.5(USB_D-) P4.5(USB_D-)
USB_P: P3.3(USB_D+) P4.3(USB_D+)
WIFI_SUSCLK: P3.50(SUSCLK) P4.50(SUSCLK)

Not connected (* = marked no-connect by the designer): DS1 C1(CATHODE1)*; P1 5(PERN3)* 6(NC)* 7(PERP3)* 8(NC)* 10(DAS/DSS#)* 11(PETN3)* 13(PETP3)* 17(PERN2)* 19(PERP2)* 23(PETN2)* 25(PETP2)* 29(PERN1)* 31(PERP1)* 35(PETN1)* 36(NC)* 37(PETP1)* 52(CLKREQ*/NC)* 53(REFCLKN)* 54(PEWAKE*/NC)* 55(REFCLKP)* 67(NC)* 69(PEDET)*; P2 5(PERN3)* 6(NC)* 7(PERP3)* 8(NC)* 10(DAS/DSS#)* 11(PETN3)* 13(PETP3)* 17(PERN2)* 19(PERP2)* 23(PETN2)* 25(PETP2)* 29(PERN1)* 31(PERP1)* 35(PETN1)* 36(NC)* 37(PETP1)* 52(CLKREQ*/NC)* 53(REFCLKN)* 54(PEWAKE*/NC)* 55(REFCLKP)* 67(NC)* 69(PEDET)*; P3 6(LED1#)* 9(SDIO_CLK)* 11(SDIO_CMD)* 13(SDIO_D0)* 15(SDIO_D1)* 16(LED2#)* 17(SDIO_D2)* 19(SDIO_D3)* 21(SDIO_WAKE#)* 23(SDIO_RESET#)* 38(RSVD/CLINK_RST)* 40(RSVD/CLINK_DATA)* 42(RSVD/CLINK_CLK)* 44(COEX3(1.8V))* 46(COEX2(1.8V))* 48(COEX1(1.8V))* 64(UART_RTS(1.8V))* 66(UIM_SWP/PERST1#)*; P4 6(LED1#)* 9(SDIO_CLK)* 11(SDIO_CMD)* 13(SDIO_D0)* 15(SDIO_D1)* 16(LED2#)* 17(SDIO_D2)* 19(SDIO_D3)* 21(SDIO_WAKE#)* 23(SDIO_RESET#)* 38(RSVD/CLINK_RST)* 40(RSVD/CLINK_DATA)* 42(RSVD/CLINK_CLK)* 44(COEX3(1.8V))* 46(COEX2(1.8V))* 48(COEX1(1.8V))* 59(RSVD/PETP1)* 61(RSVD/PETN1)* 64(UART_RTS(1.8V))* 65(RSVD/PERP1)* 67(RSVD/PERN1)* 68(UIM_PWRSNK/CLKREQ1#)* 70(UIM_PWRSRC/PEWAKE1#)* 71(RSVD/REFCLKP1)* 73(RSVD/REFCLKN1)*; U1 7(WP)*; U3 22(NC3)* 43(NC_SI_ARB_IN)* 44(NC_SI_ARB_OUT)* 56(NC1)* 58(NC2)*

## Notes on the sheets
sheet 1
- FC-OPLN Rev 1.0
sheet 4
- M.2 KEY M
- PCB EDGE CONN PADS (M.2 Key M)
- M.2 Key M SATA
- SATA ONLY
- SATA ONLY
- M.2 SATA
- Plated hole for 2242, 2260, 2280
  Drill 4.0mm
  Plated 5.0mm
sheet 5
- M.2 KEY E
- PCB EDGE CONN PADS (M.2 Key E)
- M.2 Key E, WiFi & BT
- PU on SBC
- PU on SBC, Stronger PD to activate CLK to I210 is needed
  (CLKREQ# not supported by I210).
- Direct connection to GND due
- to space considerations
- Place at 30 (2230) position
- 2230
- EEPROM
- M.2 WiFi
- DNP
- DNP
- SMB:A8h-A9h (0x54)
- DNP
- 1010 100X
sheet 6
- LAN I210IS
- DNP
- DNP
- RateSelect strap
- DNP
- I210IS
- DNP
- Flash security
  is disabled
  when the
  pin is pulled
  low.
- 33R near  Flash
- should be
  ESR<50ohm
- should be
  39nF
- STITCHING CAPACITORS
- SFP CAGE
- LAN SFP LINK LEDs
- DNP
- Dual LED used instead of single
